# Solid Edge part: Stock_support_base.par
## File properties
Title: Stock Support Base
Author: Abhinav Rai
Template: Normal.par
Last saved by: Cadcim
Revision: 19
Application: Solid Edge
Material: aluminum
Accuracy: 0.99
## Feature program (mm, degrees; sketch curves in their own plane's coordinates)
sketch for "unnamed RevolvedProtrusion 1" plane through (0, 0, 0) normal (0, -1, 0) x-axis (1, 0, 0)
  line (0, 29.2468) -> (71.7103, 29.2468)
  line (71.7103, 29.2468) -> (71.7103, 19.7218)
  line (71.7103, 19.7218) -> (165.1, -256.5032)
  line (165.1, -256.5032) -> (215.9, -256.5032)
  line (215.9, -256.5032) -> (215.9, -281.9032)
  line (215.9, -281.9032) -> (156.9298, -281.9032)
  line (156.9298, -281.9032) -> (85.052, -69.3053)
  arc centre (73.021, -73.3729) radius 12.7 from (60.325, -73.0538) to (85.052, -69.3053) cw
  line (60.325, -73.0538) -> (57.15, -199.3532)
  line (57.15, -199.3532) -> (0, -199.3532)
  line (0, 29.2468) -> (0, -199.3532)
revolve "unnamed RevolvedProtrusion 1" add full turn 360 deg
sketch for "unnamed Hole 1" plane through (0, 0, 29.2468) normal (0, 0, 1) x-axis (1, 0, 0)
  hole centre (0, 0) bore radius 38.1
hole "unnamed Hole 1" through
sketch for "ExtrudedProtrusion_2" plane through (0, 0, -256.5032) normal (0, 0, 1) x-axis (0, 1, 0)
  arc centre (0, -119.2664) radius 41.0756 from (-18.7686, -155.8034) to (18.7686, -155.8034) ccw
  line (-18.7686, -197.1314) -> (-18.7686, -155.8034)
  arc centre (0, -197.1314) radius 18.7686 from (18.7686, -197.1314) to (-18.7686, -197.1314) cw
  line (18.7686, -197.1314) -> (18.7686, -155.8034)
extrude "ExtrudedProtrusion_2" add finite 12.7 along +normal
sketch for "unnamed Hole 2" plane through (187.8036, 0, -243.8032) normal (0, 0, 1) x-axis (1, 0, 0)
hole "unnamed Hole 2" through
fillet "Round_4" radius 3.175
pattern "unnamed Pattern 1" of "ExtrudedProtrusion_2", "unnamed Hole 2", "Round_4"
pattern "unnamed Pattern 2"
sketch for "ExtrudedProtrusion_3" plane through (0, -134.62, 0) normal (0, -1, 0) x-axis (1, 0, 0)
  circle centre (0, -2.5032) radius 19.05
extrude "ExtrudedProtrusion_3" add  Plane_Distance = 134.62 mm
adv blend "unnamed AdvBlend 1"
sketch for "ExtrudedProtrusion_4" plane through (0, -134.62, -2.5032) normal (0, -1, 0) x-axis (1, 0, 0)
  circle centre (0, -3.81) radius 22.225
extrude "ExtrudedProtrusion_4" add finite 9.525 along +normal
mirror "unnamed Mirror 1" of "ExtrudedProtrusion_4", "unnamed AdvBlend 1", "ExtrudedProtrusion_3" about plane through (0, 0, 0) normal (0, -1, 0)
extrude "unnamed Protrusion 1" add
adv blend "unnamed AdvBlend 2"
extrude "unnamed Protrusion 2" add finite 9.525
sketch for "ExtrudedProtrusion_7" plane through (104.775, 0, 0) normal (1, 0, 0) x-axis (0, 1, 0)
  circle centre (0, -167.6032) radius 19.05
extrude "ExtrudedProtrusion_7" add finite 41.275 along +normal  Plane_Distance = 104.775 mm
sketch for "unnamed Hole 3" plane through (146.05, 0, -167.6032) normal (1, 0, 0) x-axis (0, 1, 0)
  hole centre (0, 0) bore radius 7.9375
hole "unnamed Hole 3" through
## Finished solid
Body 1: solid body, 54 faces, 95 edges, 41 vertices.
  Faces by surface: plane 26, cylinder 19, torus 4, cone 3, blend 2
  Edges by curve: circle 57, intersection 20, line 18
Bounding box of the edges (mm; curved faces can reach further): 431.800 x 431.800 x 311.150, from (-215.9, -215.9, -281.9032) to (215.9, 215.9, 29.2468).
Cylindrical faces by radius (mm): R7.9375 x1, R11.1125 x3, R15.875 x3, R18.7686 x3, R19.05 x4, R22.225 x2, R38.1 x1, R71.7103 x1, R215.9 x1
Conical faces (half-angle, radius in mm at the cone's reference point): 1.44 deg R60.325 x1, 18.68 deg R71.7103 x1, 18.68 deg R156.9298 x1
Toroidal faces (ring radius, tube radius in mm): R73.021 r12.7 x1, R163.0843 r3.175 x3
Planar faces by outward normal: +x 1, +y 4, +z 10, -x 1, -y 4, -z 2, oblique 4
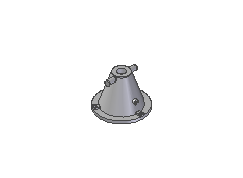
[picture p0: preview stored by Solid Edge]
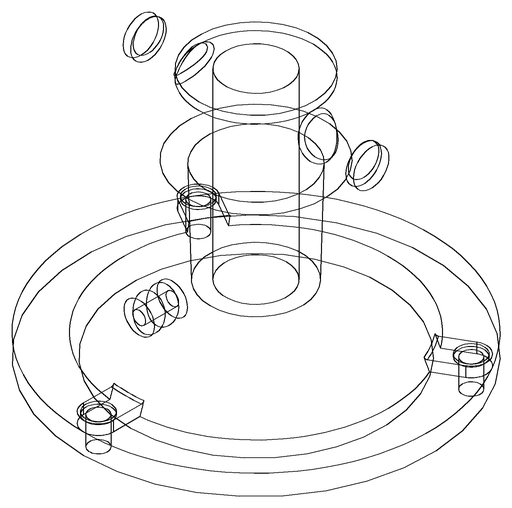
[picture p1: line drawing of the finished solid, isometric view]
